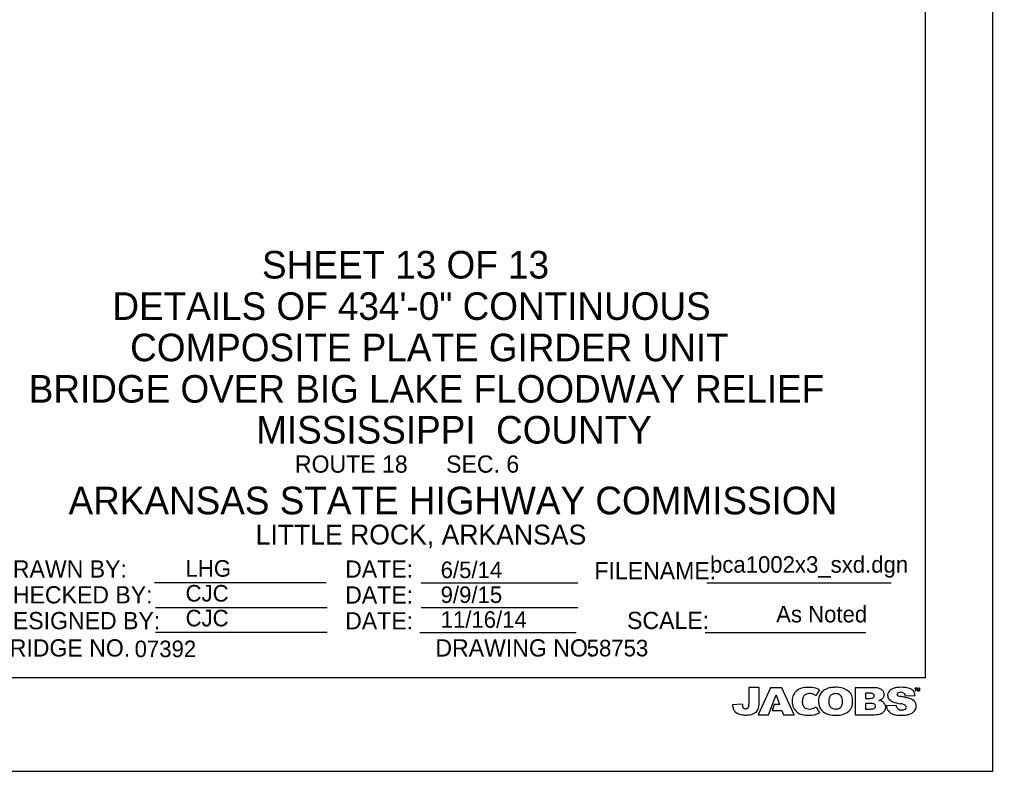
# Model space of a CAD drawing. Extents: x -1771525.8 to -1771491.7, y -422628.7 to -422606.9.
# Drawn here: x -1771498.72 to -1771491.67, y -422628.72 to -422623.26 of the extents above; entities that cross this region are included whole.
import ezdxf

# ---------------------------------------------------------------- set-up
doc = ezdxf.new("R2010")
doc.units = 0
for name, color, linetype in [('border', 7, 'Continuous'), ('Border 2660-Hwy18 - Level 62', 7, 'Continuous'), ('Border 2660-Hwy18 - Text', 7, 'Continuous'), ('Border 2660-Hwy18 - Title Text', 7, 'Continuous'), ('Bridge No BLFR', 7, 'Continuous'), ('Text', 7, 'Continuous'), ('Title Block Text', 7, 'Continuous'), ('Title Text', 7, 'Continuous')]:
    doc.layers.add(name, color=color, linetype=linetype)

msp = doc.modelspace()

# ---------------------------------------------------------------- linework, layer by layer
at = {"layer": 'border'}
for p, q in [((-1771492.1573, -422628.0376), (-1771492.1573, -422607.4924)), ((-1771497.7445, -422627.3464), (-1771496.5013, -422627.3464)), ((-1771495.8113, -422627.3475), (-1771494.6773, -422627.3475)), ((-1771493.7413, -422627.3475), (-1771492.4052, -422627.3475)), ((-1771497.7373, -422627.5264), (-1771496.4941, -422627.5264)), ((-1771495.8113, -422627.5275), (-1771494.6773, -422627.5275)), ((-1771497.7373, -422627.7064), (-1771496.4941, -422627.7064)), ((-1771495.8221, -422627.7075), (-1771494.6881, -422627.7075)), ((-1771493.7537, -422627.7075), (-1771492.5881, -422627.7075)), ((-1771492.1573, -422628.0376), (-1771524.1684, -422628.0376))]:
    msp.add_line(p, q, dxfattribs=at)
for points in [[(-1771493.3624, -422628.2172), (-1771493.3624, -422628.1071), (-1771493.4365, -422628.1071), (-1771493.4365, -422628.2278)], [(-1771493.2396, -422628.1597), (-1771493.2136, -422628.2302), (-1771493.2523, -422628.2302), (-1771493.2683, -422628.2726), (-1771493.1982, -422628.2726), (-1771493.1864, -422628.3049), (-1771493.1089, -422628.3049), (-1771493.1985, -422628.1089), (-1771493.2792, -422628.1089), (-1771493.3691, -422628.3049), (-1771493.2934, -422628.3049), (-1771493.2396, -422628.1597)], [(-1771492.5233, -422628.1089), (-1771492.6655, -422628.1089), (-1771492.6655, -422628.3049)], [(-1771492.5584, -422628.1485), (-1771492.591, -422628.1485), (-1771492.591, -422628.1858)], [(-1771492.3003, -422628.1673), (-1771492.2305, -422628.164)], [(-1771492.2187, -422628.1113), (-1771492.2338, -422628.1113), (-1771492.2338, -422628.1132), (-1771492.2277, -422628.1132), (-1771492.2277, -422628.1301), (-1771492.225, -422628.1301), (-1771492.225, -422628.1132), (-1771492.2187, -422628.1132), (-1771492.2187, -422628.1113)], [(-1771492.2141, -422628.1144), (-1771492.2141, -422628.1144), (-1771492.2081, -422628.1301), (-1771492.2063, -422628.1301), (-1771492.2002, -422628.1144), (-1771492.2002, -422628.1144), (-1771492.2002, -422628.1301), (-1771492.1978, -422628.1301), (-1771492.1978, -422628.1113), (-1771492.2011, -422628.1113), (-1771492.2072, -422628.1271), (-1771492.2132, -422628.1113), (-1771492.2165, -422628.1113), (-1771492.2165, -422628.1301), (-1771492.2141, -422628.1301), (-1771492.2141, -422628.1144)], [(-1771493.484, -422628.2287), (-1771493.5548, -422628.2323)], [(-1771492.591, -422628.1858), (-1771492.5566, -422628.1858)], [(-1771492.5535, -422628.2233), (-1771492.591, -422628.2233), (-1771492.591, -422628.2629)], [(-1771492.3693, -422628.2366), (-1771492.4395, -422628.2402)], [(-1771492.6655, -422628.3049), (-1771492.5378, -422628.3049)], [(-1771492.591, -422628.2629), (-1771492.5529, -422628.2629)]]:
    msp.add_lwpolyline(points, dxfattribs=at)
for centre, radius, start, end in [((-1771493.0242, -422628.2018), 0.0987, 155.24445, 178.6811), ((-1771493.0404, -422628.1944), 0.0809, 126.85134, 155.24445), ((-1771493.0208, -422628.2206), 0.1137, 94.78534, 126.85134), ((-1771493.021, -422628.184), 0.0243, 134.3139, 161.28337), ((-1771492.9991, -422628.2064), 0.0556, 110.76549, 134.31389), ((-1771493, -422628.4689), 0.3629, 86.90301, 94.78534), ((-1771493, -422628.2039), 0.0529, 91.50728, 110.76549), ((-1771492.9984, -422628.2668), 0.1159, 82.6359, 91.50728), ((-1771492.9898, -422628.2007), 0.0493, 65.55483, 82.6359), ((-1771492.9865, -422628.219), 0.1126, 56.9246, 86.90301), ((-1771493.0186, -422628.2639), 0.1187, 54.60016, 65.55482), ((-1771492.7001, -422628.2842), 0.2758, 144.63502, 154.88444), ((-1771492.8315, -422628.2045), 0.1003, 148.62486, 181.28594), ((-1771492.8527, -422628.1916), 0.0755, 123.8806, 148.62486), ((-1771492.8155, -422628.2469), 0.1421, 111.71043, 123.8806), ((-1771492.8276, -422628.2166), 0.1094, 96.53712, 111.71043), ((-1771492.8257, -422628.1865), 0.0287, 136.11771, 160.86113), ((-1771492.8091, -422628.2025), 0.0518, 117.7176, 136.11771), ((-1771492.7964, -422628.4891), 0.3838, 91.9058, 96.53711), ((-1771492.8154, -422628.1905), 0.0382, 100.21085, 117.7176), ((-1771492.8063, -422628.2409), 0.0895, 90.96753, 100.21085), ((-1771492.8021, -422628.2715), 0.1661, 73.44767, 92.42532), ((-1771492.8074, -422628.2137), 0.0622, 67.07702, 90.42176), ((-1771492.7982, -422628.192), 0.0386, 24.62738, 67.07702), ((-1771492.7867, -422628.2198), 0.1121, 41.1934, 73.44767), ((-1771492.746, -422628.1841), 0.0579, 18.69658, 41.1934), ((-1771492.8147, -422628.2073), 0.1305, 344.57078, 18.69658), ((-1771492.5599, -422628.2837), 0.1352, 86.2098, 89.3498), ((-1771492.5544, -422628.2002), 0.0514, 74.87225, 86.2098), ((-1771492.5461, -422628.1695), 0.0196, 40.24248, 74.87225), ((-1771492.5393, -422628.1638), 0.0108, 21.96041, 40.24248), ((-1771492.5474, -422628.167), 0.0195, 341.46246, 21.96041), ((-1771492.5232, -422628.2126), 0.1036, 72.18854, 90.1477), ((-1771492.5099, -422628.1714), 0.0603, 61.48438, 72.18854), ((-1771492.5081, -422628.168), 0.0564, 34.7868, 61.48438), ((-1771492.4876, -422628.1537), 0.0315, 16.94547, 34.7868), ((-1771492.5011, -422628.1578), 0.0455, 347.09493, 16.94546), ((-1771492.389, -422628.1638), 0.0416, 177.64848, 218.85347), ((-1771492.3831, -422628.164), 0.0476, 124.07995, 177.64848), ((-1771492.3519, -422628.2101), 0.1032, 108.28083, 124.07995), ((-1771492.3588, -422628.1891), 0.0811, 99.81734, 108.28082), ((-1771492.3313, -422628.3481), 0.2425, 93.402, 99.81734), ((-1771492.3544, -422628.1572), 0.00815, 165.3108, 208.28871), ((-1771492.3468, -422628.1592), 0.016, 146.47062, 165.31079), ((-1771492.3472, -422628.1522), 0.0169, 211.74165, 226.63389), ((-1771492.3528, -422628.1552), 0.00877, 130.78548, 146.47062), ((-1771492.3488, -422628.1539), 0.0145, 226.63389, 245.14291), ((-1771492.3418, -422628.1679), 0.0256, 97.30547, 130.78548), ((-1771492.3319, -422628.1173), 0.0549, 245.14291, 260.98065), ((-1771492.3306, -422628.3595), 0.2539, 80.65488, 93.40199), ((-1771492.3363, -422628.2112), 0.0692, 81.32121, 97.30546), ((-1771492.3313, -422628.1783), 0.0359, 57.47403, 81.32121), ((-1771492.3228, -422628.165), 0.0202, 37.19775, 57.47403), ((-1771492.3347, -422628.174), 0.0351, 11.00509, 37.19775), ((-1771492.304, -422628.1974), 0.0897, 57.59056, 80.65488), ((-1771492.2824, -422628.1634), 0.0494, 39.0736, 57.59056), ((-1771492.2916, -422628.1708), 0.0612, 6.43854, 39.0736), ((-1771493.4328, -422628.2228), 0.1226, 184.56975, 198.10689), ((-1771493.4236, -422628.2307), 0.0602, 178.25555, 191.49609), ((-1771493.5157, -422628.2281), 0.0792, 349.15753, 360), ((-1771493.486, -422628.2213), 0.1237, 351.37058, 1.82911), ((-1771492.9698, -422628.2031), 0.1532, 178.6811, 194.39118), ((-1771492.964, -422628.209), 0.0855, 178.67021, 195.85307), ((-1771492.9458, -422628.2095), 0.1037, 161.28337, 178.67021), ((-1771493.0058, -422628.2209), 0.0421, 195.85308, 214.53695), ((-1771492.7795, -422628.2033), 0.1523, 181.28594, 193.19556), ((-1771492.7662, -422628.2071), 0.0917, 160.86113, 181.29811), ((-1771492.7628, -422628.2071), 0.0951, 181.29811, 197.94918), ((-1771492.8248, -422628.2272), 0.0299, 197.94918, 222.77411), ((-1771492.7963, -422628.2249), 0.036, 299.54008, 342.40029), ((-1771492.814, -422628.1992), 0.056, 2.74416, 24.62738), ((-1771492.8487, -422628.2082), 0.091, 342.40029, 0.08449), ((-1771493.0072, -422628.2085), 0.2494, 0.08449, 2.74416), ((-1771492.5566, -422628.1224), 0.0633, 270.03631, 284.14376), ((-1771492.5583, -422628.4701), 0.2471, 86.68376, 88.87562), ((-1771492.5469, -422628.273), 0.0497, 75.93141, 86.68375), ((-1771492.546, -422628.1647), 0.0196, 284.14376, 307.88655), ((-1771492.5428, -422628.2567), 0.0328, 59.62021, 75.9314), ((-1771492.543, -422628.1685), 0.0149, 307.88655, 341.46246), ((-1771492.5338, -422628.2413), 0.015, 30.83409, 59.62021), ((-1771492.5361, -422628.2427), 0.0177, 337.50371, 30.83409), ((-1771492.5135, -422628.1277), 0.0753, 284.67851, 296.84115), ((-1771492.5105, -422628.2912), 0.092, 61.0815, 79.92424), ((-1771492.5008, -422628.1529), 0.0471, 296.84115, 329.81819), ((-1771492.4849, -422628.2447), 0.039, 44.97734, 61.0815), ((-1771492.4866, -422628.1611), 0.0307, 329.81819, 347.09492), ((-1771492.4893, -422628.2491), 0.0452, 342.98447, 44.97734), ((-1771492.3774, -422628.1544), 0.0566, 218.85347, 233.65492), ((-1771492.3637, -422628.1358), 0.0797, 233.65493, 244.76888), ((-1771492.331, -422628.0665), 0.1563, 244.76888, 253.47301), ((-1771492.2835, -422627.9063), 0.3234, 253.47301, 259.82965), ((-1771492.3177, -422628.2288), 0.0523, 188.51407, 201.638), ((-1771492.393, -422628.5165), 0.2966, 76.01042, 79.82965), ((-1771492.4156, -422628.6449), 0.4794, 77.5139, 80.98065), ((-1771492.3448, -422628.3233), 0.0974, 67.95933, 76.01043), ((-1771492.7394, -422630.1073), 1.9772, 76.80348, 77.5139), ((-1771492.3182, -422628.2575), 0.0265, 39.93128, 67.95933), ((-1771492.3253, -422628.3411), 0.1631, 65.69981, 76.80348), ((-1771492.2901, -422628.2632), 0.0776, 51.35648, 65.6998), ((-1771492.2743, -422628.2435), 0.0523, 36.51625, 51.35648), ((-1771492.2713, -422628.2412), 0.0486, 345.16113, 36.51625), ((-1771493.4993, -422628.2445), 0.0527, 198.1069, 225.97986), ((-1771493.4805, -422628.2251), 0.0797, 225.97986, 261.07142), ((-1771493.455, -422628.0626), 0.2441, 261.07143, 269.94051), ((-1771493.4556, -422628.2372), 0.0277, 191.49609, 218.75114), ((-1771493.4644, -422628.2443), 0.0164, 218.75114, 257.48803), ((-1771493.4604, -422628.2266), 0.0345, 257.48804, 275.78339), ((-1771493.4596, -422628.2354), 0.0257, 275.78339, 301.69258), ((-1771493.4551, -422628.1397), 0.1671, 269.94051, 279.1616), ((-1771493.4525, -422628.2468), 0.0122, 301.69258, 325.41713), ((-1771493.4659, -422628.2376), 0.0285, 325.41713, 349.15753), ((-1771493.4433, -422628.2127), 0.0931, 279.1616, 305.86462), ((-1771493.423, -422628.2407), 0.0585, 305.86462, 338.78432), ((-1771493.4176, -422628.2428), 0.0527, 338.78433, 350.09512), ((-1771493.9067, -422628.1574), 0.5492, 350.09512, 351.37058), ((-1771493.0618, -422628.2267), 0.0582, 194.39118, 214.17986), ((-1771493.0051, -422628.1882), 0.1268, 214.17986, 231.66155), ((-1771493.0363, -422628.2276), 0.0765, 231.66155, 258.68595), ((-1771492.9928, -422628.0104), 0.298, 258.68595, 268.81632), ((-1771493.0084, -422628.2227), 0.0388, 214.53695, 253.19175), ((-1771492.9974, -422628.1863), 0.0769, 253.19175, 291.19559), ((-1771492.996, -422628.1627), 0.1457, 268.81632, 299.38782), ((-1771493.0032, -422628.1715), 0.0928, 291.19559, 305.51438), ((-1771492.5861, -422628.0642), 0.4066, 206.7197, 213.67795), ((-1771492.8612, -422628.2225), 0.0683, 193.19556, 217.74992), ((-1771492.8276, -422628.1964), 0.1109, 217.74992, 244.17034), ((-1771492.8385, -422628.219), 0.0859, 244.17034, 259.49425), ((-1771492.7995, -422628.0091), 0.2993, 259.49425, 268.64264), ((-1771492.812, -422628.2153), 0.0474, 222.77411, 250.19554), ((-1771492.8109, -422628.2122), 0.0507, 250.19554, 269.12639), ((-1771492.8088, -422628.0718), 0.1911, 269.12639, 272.0424), ((-1771492.8024, -422628.1285), 0.1799, 268.64264, 285.90168), ((-1771492.8038, -422628.2116), 0.0512, 272.0424, 299.54008), ((-1771492.7806, -422628.2048), 0.1005, 285.90169, 322.67136), ((-1771492.7562, -422628.2235), 0.0698, 322.67136, 344.57078), ((-1771492.5532, -422628.1589), 0.104, 270.00009, 276.67494), ((-1771492.5461, -422628.2195), 0.043, 276.67494, 293.06453), ((-1771492.5481, -422627.967), 0.3381, 271.72242, 279.62791), ((-1771492.5362, -422628.2426), 0.0178, 293.06453, 337.5037), ((-1771492.5017, -422628.2403), 0.0609, 279.62791, 313.6357), ((-1771492.4949, -422628.2474), 0.0511, 313.6357, 342.98447), ((-1771492.0634, -422628.1873), 0.3799, 187.9971, 189.09474), ((-1771492.3889, -422628.2394), 0.0503, 189.09474, 202.46404), ((-1771492.354, -422628.225), 0.0881, 202.46404, 215.89258), ((-1771492.375, -422628.2402), 0.0621, 215.89258, 243.29677), ((-1771492.3623, -422628.2148), 0.0904, 243.29677, 257.45982), ((-1771492.3357, -422628.0954), 0.2128, 257.45982, 268.86561), ((-1771492.3366, -422628.2363), 0.0319, 201.638, 242.36347), ((-1771492.3306, -422628.2247), 0.045, 242.36347, 264.62285), ((-1771492.3284, -422627.7272), 0.5811, 268.86561, 270.76117), ((-1771492.3272, -422628.1892), 0.0806, 264.62285, 273.90099), ((-1771492.3249, -422628.2234), 0.0464, 273.901, 289.19251), ((-1771492.3231, -422628.1309), 0.1774, 270.76117, 282.50008), ((-1771492.3183, -422628.2423), 0.0263, 289.19251, 322.56596), ((-1771492.309, -422628.2498), 0.0145, 2.18131, 39.93128), ((-1771492.3086, -422628.2498), 0.0141, 322.56597, 2.18131), ((-1771492.3083, -422628.1977), 0.109, 282.50008, 295.61438), ((-1771492.2945, -422628.2263), 0.0772, 295.61437, 314.02195), ((-1771492.2831, -422628.2381), 0.0608, 314.02195, 345.16113)]:
    msp.add_arc(centre, radius, start, end, dxfattribs=at)
at = {"layer": 'Border 2660-Hwy18 - Level 62'}
msp.add_lwpolyline([(-1771525.7885, -422606.9067), (-1771491.6701, -422606.9067), (-1771491.6701, -422628.7162), (-1771525.7885, -422628.7162)], close=True, dxfattribs=at)

# ---------------------------------------------------------------- texts
at = {"layer": 'Border 2660-Hwy18 - Text'}
for s, p in [('DRAWN BY:', (-1771498.8929, -422627.3099)), ('DATE:', (-1771496.3633, -422627.3109)), ('FILENAME:', (-1771494.5563, -422627.323)), ('CHECKED BY:', (-1771498.8929, -422627.4974)), ('DATE:', (-1771496.3633, -422627.4984)), ('DESIGNED BY:', (-1771498.8929, -422627.6849)), ('DATE:', (-1771496.3633, -422627.6859)), ('SCALE:', (-1771494.3197, -422627.683)), ('BRIDGE NO.', (-1771498.9064, -422627.8825)), ('DRAWING NO.', (-1771495.7089, -422627.8824))]:
    msp.add_text(s, height=0.125, dxfattribs=at).set_placement(p)
at = {"layer": 'Border 2660-Hwy18 - Title Text'}
for s, height, p in [('MISSISSIPPI  COUNTY', 0.199999, (-1771497.0082, -422626.3386)), ('ROUTE 18      SEC. 6', 0.125, (-1771496.7274, -422626.5496)), ('ARKANSAS STATE HIGHWAY COMMISSION', 0.199999, (-1771498.3686, -422626.8512)), ('LITTLE ROCK, ARKANSAS', 0.144, (-1771497.0125, -422627.0704))]:
    msp.add_text(s, height=height, dxfattribs=at).set_placement(p)
at = {"layer": 'Bridge No BLFR'}
msp.add_text('07392', height=0.12, dxfattribs=at).set_placement((-1771497.8895, -422627.887))
at = {"layer": 'Text'}
for s, p in [('LHG', (-1771497.5203, -422627.3038)), ('6/5/14', (-1771495.6711, -422627.3142)), ('CJC', (-1771497.5203, -422627.4838)), ('9/9/15', (-1771495.6711, -422627.4942)), ('As Noted', (-1771493.2389, -422627.635)), ('CJC', (-1771497.5203, -422627.6638)), ('11/16/14', (-1771495.6711, -422627.6742))]:
    msp.add_text(s, height=0.12, dxfattribs=at).set_placement(p)
at = {"layer": 'Title Block Text'}
for s, p in [('bca1002x3_sxd.dgn', (-1771493.7181, -422627.275)), ('58753', (-1771494.6122, -422627.8813))]:
    msp.add_text(s, height=0.12, dxfattribs=at).set_placement(p)
at = {"layer": 'Title Text'}
for s, p in [('SHEET 13 OF 13', (-1771496.9661, -422625.1419)), ('DETAILS OF 434\'-0" CONTINUOUS', (-1771498.0506, -422625.4419)), ('COMPOSITE PLATE GIRDER UNIT', (-1771497.9221, -422625.7419)), ('BRIDGE OVER BIG LAKE FLOODWAY RELIEF', (-1771498.657, -422626.0419))]:
    msp.add_text(s, height=0.199999, dxfattribs=at).set_placement(p)

doc.saveas('drawing.dxf')
